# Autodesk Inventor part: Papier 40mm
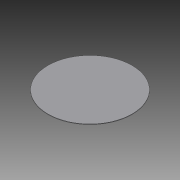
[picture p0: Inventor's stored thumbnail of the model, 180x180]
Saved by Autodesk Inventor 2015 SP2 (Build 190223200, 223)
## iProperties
Created: 2015-09
Part Number: Papier 40mm
Material: Allgemein
Document SubType Name: Modeling
Designer: ryll
Density: 1 g/cm^3
Appearance: Vorgabe
Mass: 0.502538 g
Surface Area: 40.6488 cm^2
Volume: 0.502538 cm^3
Author: ryll
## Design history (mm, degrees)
sketch "Skizze1"
  geometry: L1 (-28, 0)-(28, 0) reference; L2 (0, 28)-(0, -28) reference; C1 r 20 at (0, 0)
  constraints: 2 midpoint, 1 centre point
  dimensions: "d6" = 40 diameter of C1
extrude "Extrusion1" new body sketch "Skizze1" distance "d4" = 0.25; taper "d5" = 0 deg
node "Volumenkörper1"
